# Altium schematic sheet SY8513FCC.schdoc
size 127 x 101 mm
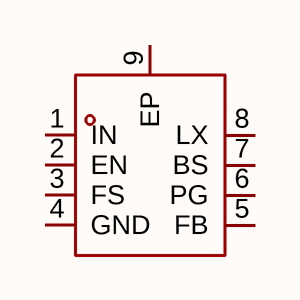
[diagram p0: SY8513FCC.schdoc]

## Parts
U?  sy8513fcc  [SOP-8_L4.9-W3.9-P1.27-LS6.0-BL-EP3.1]  (value not drawn)

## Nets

Not connected (* = marked no-connect by the designer): U? 1(IN) 2(EN) 3(FS) 4(GND) 5(FB) 6(PG) 7(BS) 8(LX) 9(EP)

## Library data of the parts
U? = sy8513fcc: 功能类型:降压型;工作电压:4.5V~100V;输出电压:-;输出电流:3A;输出类型:可调;; Manufacturer: Silergy(矽力杰); AddInBom: yes; ModelId: ff30b97526f648bb8fc48ff3f6aa1297; ModelTransform: 192.913,236.22,0,0,0,0,0,0,0; Function: 降压型; Output Current: 3A; Frequency - Switching: 100kHz~500kHz; Synchronous Rectifier: 否; Number of Outputs: 1; Topology: 降压式; Quiescent Current: 100uA; Switch tube (built-in/external): 内置; Output Type: 可调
